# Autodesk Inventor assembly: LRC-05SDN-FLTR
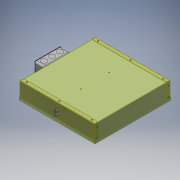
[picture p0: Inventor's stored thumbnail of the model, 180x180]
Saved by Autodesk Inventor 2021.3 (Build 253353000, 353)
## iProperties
Part Number: LRC-05SDN-FLTR
Document SubType Name: Assembly
Designer: JChurch
Author: JChurch
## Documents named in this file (5)
- X:\Revit Files\0000-Un-Zipped\COB\LRC-05SDN-FLT\LRC-05SDN-FLTR.iam
- X:\INVENTOR\830\830399-00-00.ipt
- X:\INVENTOR\885\885000-00-00.iam
- X:\INVENTOR\750\750938-00-XX.iam
- X:\INVENTOR\KIRLIN_ENG\725\725075-02-00.ipt
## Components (4 placed, 4 different names)
1. 830399-00-00:1 — Mate:1, Mate:2, Mate:3, Mate:4, Mate:5, Angle:1, Insert:2
2. 885000-00-00:1 [sub-assembly] — Mate:4, Mate:5, Angle:1
3. 750938-00-XX:1 [sub-assembly] — Insert:1, Insert:2
4. 725075-02-00:1 — Insert:1
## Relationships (8: Mate 5, Insert 2, Angle 1)
- Mate:1: 830399-00-00:1
- Mate:2: 830399-00-00:1
- Mate:3: 830399-00-00:1
- Mate:4: 830399-00-00:1 ↔ 885000-00-00:1
- Mate:5: 830399-00-00:1 ↔ 885000-00-00:1
- Angle:1: 830399-00-00:1 ↔ 885000-00-00:1
- Insert:1: 750938-00-XX:1 ↔ 725075-02-00:1
- Insert:2: 830399-00-00:1 ↔ 750938-00-XX:1
